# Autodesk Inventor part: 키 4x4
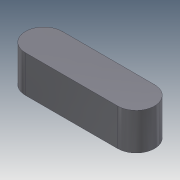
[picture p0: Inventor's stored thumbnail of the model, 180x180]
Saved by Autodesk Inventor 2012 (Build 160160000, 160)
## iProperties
Company: 한국ATC센터
Created: 2014-10
Part Number: 키 4x4
Document SubType Name: Modeling
Designer: KYOUNG IL JANG
Density: 1 g/cm^3
Mass: 0.210265 g
Surface Area: 2.35398 cm^2
Volume: 0.210265 cm^3
Material: 기본값
Author: KYOUNG IL JANG
Revision Number: 1
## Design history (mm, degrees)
sketch "스케치1"
  geometry: L1 (-5, -2)-(5, -2); L2 (5, 2)-(-5, 2); A1 r 2 centre (5, 0) between (5, -2) and (5, 2); A2 r 2 centre (-5, 0) between (-5, 2) and (-5, -2); 2 further points
  constraints: 4 end point, 4 point on circle, 4 tangent, 2 centre point, 1 horizontal, 1 horizontal alignment, 1 midpoint, 1 parallel, 1 vertical alignment
  dimensions: "d0" = 4 distance between parallel lines of L1 L2; "d1" = 14 dimension on A1 A2
extrude "돌출1" new body sketch "스케치1" stored distance "d2" = 4; taper "d3" = 0 deg
node "솔리드1"
